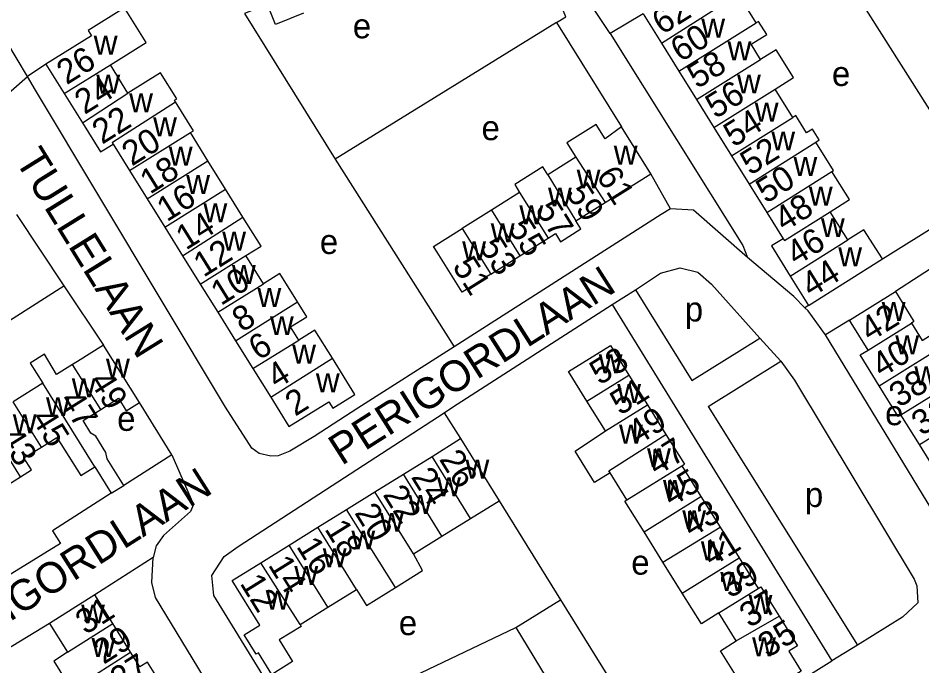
# Model space of a CAD drawing. Extents: x 157768 to 159790, y 387230 to 389604.
# Drawn here: x 158348.2 to 158494.9, y 388182.9 to 388288 of the extents above; entities that cross this region are included whole.
import ezdxf

# ---------------------------------------------------------------- set-up
doc = ezdxf.new("R2010")
doc.units = 0
for name, color, linetype in [('BLT_Basislijn', 7, 'Continuous'), ('BLT_Bebouwing', 7, 'Continuous'), ('BLT_Centroide', 7, 'Continuous'), ('BLT_Huisnummer', 7, 'Continuous'), ('BLT_Huisnummer_ tussenligend', 7, 'Continuous'), ('BLT_Onderverdeling_panden', 7, 'Continuous'), ('BLT_Straatnaam', 7, 'Continuous'), ('BLT_Vlakafsluiter', 7, 'Continuous')]:
    doc.layers.add(name, color=color, linetype=linetype)

msp = doc.modelspace()

# ---------------------------------------------------------------- linework, layer by layer
at = {"layer": 'BLT_Basislijn'}
for p, q in [((158384.98, 388288.7), (158399.69, 388265.08)), ((158449.67, 388288.69), (158444.32, 388285.49)), ((158435.6, 388287.24), (158399.69, 388265.08)), ((158435.6, 388287.24), (158446.18, 388270.31)), ((158352.71, 388280.51), (158349.72, 388278.49)), ((158399.69, 388265.08), (158418.98, 388234.63)), ((158454.1, 388257.02), (158450.94, 388262.72)), ((158488.57, 388248.89), (158505.07, 388259.33)), ((158347.92, 388256.11), (158355.63, 388244.55)), ((158507.94, 388254.9), (158490.64, 388243.59)), ((158312.55, 388217.11), (158355.63, 388244.55)), ((158355.63, 388244.55), (158362.06, 388234.91)), ((158444.66, 388241.5), (158448.43, 388243.86)), ((158448.43, 388243.86), (158457.61, 388229.19)), ((158444.66, 388241.5), (158480.34, 388183.69)), ((158476.52, 388241.37), (158475.94, 388240.99)), ((158483.19, 388238.98), (158479.29, 388236.6)), ((158497.32, 388207), (158479.29, 388236.6)), ((158457.61, 388229.19), (158468.65, 388236.06)), ((158460.26, 388224.95), (158472.05, 388232.29)), ((158373.16, 388217.13), (158367.88, 388225.6)), ((158460.26, 388224.95), (158484.49, 388186.23)), ((158417.37, 388223.95), (158420.03, 388219.74)), ((158373.16, 388217.13), (158365.35, 388212.14)), ((158426.29, 388209.66), (158436.28, 388193.58)), ((158370.1, 388200.44), (158360.66, 388194.37)), ((158428.99, 388189.09), (158436.28, 388193.58)), ((158436.28, 388193.58), (158453.03, 388166.65)), ((158353.29, 388189.74), (158336.07, 388179.24)), ((158408.94, 388179.51), (158428.99, 388189.09)), ((158428.99, 388189.09), (158445.59, 388162)), ((158484.49, 388186.23), (158480.34, 388183.69))]:
    msp.add_line(p, q, dxfattribs=at)
for points in [[(158349.72, 388278.49), (158346.36, 388284.12), (158345.87, 388286.78), (158346.16, 388288.41), (158347.49, 388290.13), (158351.49, 388293.04), (158382.15, 388309.1), (158406.63, 388320.52), (158418.95, 388325.92), (158458.67, 388342.3), (158495.06, 388356.91), (158496.09, 388357.31), (158498.9, 388357.63), (158500.72, 388357.63), (158504.55, 388356.37)], [(158444.32, 388285.49), (158436.68, 388296.95), (158434.42, 388302.8)], [(158435.6, 388287.24), (158437.14, 388288.19), (158431.35, 388302.19)], [(158497.8, 388270.57), (158497.61, 388270.86), (158478.88, 388300.51)], [(158444.32, 388285.49), (158465.87, 388251.07), (158466.61, 388249.14)], [(158418.98, 388234.63), (158403.33, 388224.67), (158396.24, 388220.06), (158392.33, 388217.68), (158390.41, 388216.95), (158389.21, 388216.88), (158387.35, 388217.31), (158386.16, 388218.18), (158381.87, 388224.86), (158351.02, 388276.29), (158349.72, 388278.49)], [(158454.1, 388257.02), (158452.61, 388256.13), (158418.98, 388234.63)], [(158466.61, 388249.14), (158457.87, 388256.8), (158454.1, 388257.02)], [(158475.94, 388240.99), (158474.13, 388242.81), (158466.61, 388249.14)], [(158448.43, 388243.86), (158452.5, 388246.58), (158455.69, 388247.43), (158458.57, 388246.74), (158460.76, 388244.81), (158468.65, 388236.06)], [(158417.37, 388223.95), (158418.74, 388224.84), (158444.66, 388241.5)], [(158479.29, 388236.6), (158476.45, 388240.48), (158475.94, 388240.99)], [(158468.65, 388236.06), (158472.05, 388232.29)], [(158472.05, 388232.29), (158474.24, 388229.24), (158493.66, 388196.96), (158494.14, 388195.85), (158494.27, 388193.09), (158491.78, 388190.76), (158484.49, 388186.23)], [(158395.91, 388168.42), (158379.98, 388194.29), (158379.66, 388197.53), (158381.67, 388200.59), (158383.9, 388202.25), (158417.37, 388223.95)], [(158373.16, 388217.13), (158376.69, 388209.04), (158376.21, 388207.92), (158371.8, 388204.02), (158370.63, 388202.35), (158370.1, 388200.44)], [(158363.32, 388210.88), (158353.8, 388204.8), (158355.1, 388202.71), (158342.47, 388194.97)], [(158385.74, 388166.03), (158387, 388166.8), (158370.49, 388193.98), (158369.92, 388196.38), (158370.1, 388200.44)], [(158453.03, 388166.65), (158454.49, 388167.56), (158480.34, 388183.69)]]:
    msp.add_lwpolyline(points, dxfattribs=at)
at = {"layer": 'BLT_Bebouwing'}
for p, q in [((158449.67, 388288.69), (158452.64, 388283.92)), ((158452.64, 388283.92), (158455.48, 388279.37)), ((158352.71, 388280.51), (158355.68, 388275.76)), ((158366.02, 388275.82), (158363.18, 388280.38)), ((158455.48, 388279.37), (158458.33, 388274.78)), ((158473.97, 388271.85), (158471.11, 388276.44)), ((158355.68, 388275.76), (158358.64, 388271.01)), ((158458.33, 388274.78), (158461.18, 388270.2)), ((158379.02, 388264.8), (158376.17, 388269.39)), ((158450.94, 388262.72), (158446.18, 388270.31)), ((158461.18, 388270.2), (158464.04, 388265.61)), ((158363.62, 388267.52), (158366.29, 388263.24)), ((158381.87, 388260.24), (158379.02, 388264.8)), ((158438.76, 388265.41), (158434.21, 388262.56)), ((158464.04, 388265.61), (158466.89, 388261.04)), ((158366.29, 388263.24), (158369.14, 388258.67)), ((158443.53, 388258.08), (158450.94, 388262.72)), ((158384.7, 388255.69), (158381.87, 388260.24)), ((158466.89, 388261.04), (158469.74, 388256.45)), ((158369.14, 388258.67), (158372, 388254.07)), ((158429.63, 388259.69), (158425.07, 388256.83)), ((158438.74, 388255.07), (158443.53, 388258.08)), ((158425.07, 388256.83), (158420.3, 388253.83)), ((158469.74, 388256.45), (158472.4, 388252.18)), ((158482.94, 388251.99), (158480.02, 388256.54)), ((158374.9, 388249.42), (158377.78, 388244.8)), ((158388.04, 388244.87), (158385.18, 388249.44)), ((158424.94, 388246.43), (158429.68, 388249.4)), ((158476.52, 388241.37), (158488.57, 388248.89)), ((158473.56, 388246.12), (158476.52, 388241.37)), ((158377.78, 388244.8), (158380.62, 388240.24)), ((158483.19, 388238.98), (158490.64, 388243.59)), ((158380.62, 388240.24), (158383.49, 388235.63)), ((158486.21, 388234.12), (158483.19, 388238.98)), ((158383.49, 388235.63), (158386.31, 388231.12)), ((158367.88, 388225.6), (158362.06, 388234.91)), ((158386.31, 388231.12), (158389.21, 388226.47)), ((158447.37, 388230.05), (158450.37, 388225.23)), ((158352.2, 388228.75), (158347.38, 388225.73)), ((158443.57, 388220.99), (158440.56, 388225.81)), ((158450.37, 388225.23), (158453.37, 388220.42)), ((158415.4, 388216.86), (158420.03, 388219.74)), ((158453.37, 388220.42), (158456.37, 388215.6)), ((158497.26, 388214.39), (158494.53, 388218.79)), ((158410.77, 388213.98), (158415.4, 388216.86)), ((158360.63, 388215.18), (158363.32, 388210.88)), ((158455.95, 388215.34), (158456.37, 388215.6)), ((158455.95, 388215.34), (158459.05, 388210.36)), ((158406.13, 388211.1), (158410.77, 388213.98)), ((158363.32, 388210.88), (158365.35, 388212.14)), ((158401.5, 388208.23), (158406.13, 388211.1)), ((158459.05, 388210.36), (158462.16, 388205.38)), ((158421.66, 388206.79), (158426.29, 388209.66)), ((158396.86, 388205.35), (158401.5, 388208.23)), ((158417.02, 388203.91), (158421.66, 388206.79)), ((158392.23, 388202.47), (158396.86, 388205.35)), ((158462.16, 388205.38), (158465.26, 388200.4)), ((158412.39, 388201.03), (158417.02, 388203.91)), ((158387.59, 388199.59), (158392.23, 388202.47)), ((158465.26, 388200.4), (158468.36, 388195.41)), ((158360.66, 388194.37), (158353.29, 388189.74)), ((158363.56, 388189.74), (158360.66, 388194.37)), ((158398.49, 388192.39), (158403.12, 388195.27)), ((158394, 388189.6), (158398.49, 388192.39)), ((158464.81, 388186.92), (158461.99, 388191.45)), ((158366.47, 388185.11), (158363.56, 388189.74))]:
    msp.add_line(p, q, dxfattribs=at)
for points in [[(158468.03, 388287.19), (158465.14, 388291.84), (158462.61, 388290.24)], [(158365.47, 388289.67), (158359.55, 388285.99), (158360.09, 388285.11), (158352.71, 388280.51)], [(158363.18, 388280.38), (158369.01, 388284.03), (158365.47, 388289.67)], [(158394.54, 388288.77), (158389.99, 388286.93), (158388.67, 388290.19), (158384.98, 388288.7)], [(158468.76, 388281.28), (158467.21, 388283.77), (158469.74, 388285.34), (158468.43, 388287.44), (158468.03, 388287.19)], [(158471.11, 388276.44), (158474.11, 388278.32), (158471.3, 388282.85), (158468.76, 388281.28)], [(158373.76, 388274.37), (158373.59, 388274.64), (158373.96, 388274.87), (158371.31, 388279.12), (158366.02, 388275.82)], [(158376.17, 388269.39), (158376.67, 388269.7), (158373.76, 388274.37)], [(158477.71, 388267.85), (158478.27, 388268.2), (158477.16, 388269.98), (158476.18, 388269.37), (158474.45, 388272.15), (158473.97, 388271.85)], [(158358.64, 388271.01), (158361.6, 388266.26), (158363.62, 388267.52)], [(158446.18, 388270.31), (158443.53, 388268.4), (158442.07, 388270.73), (158437.3, 388267.74), (158438.76, 388265.41)], [(158480.31, 388263.08), (158480.59, 388263.26), (158477.71, 388267.85)], [(158434.21, 388262.56), (158433.42, 388263.83), (158428.84, 388260.96), (158429.63, 388259.69)], [(158480.02, 388256.54), (158483.17, 388258.52), (158480.31, 388263.08)], [(158385.18, 388249.44), (158387.64, 388250.97), (158384.7, 388255.69)], [(158434.26, 388252.27), (158435.43, 388253), (158436.25, 388251.7), (158439.55, 388253.77), (158438.74, 388255.07)], [(158372, 388254.07), (158374.9, 388249.42)], [(158424.94, 388246.43), (158420.29, 388243.51), (158416.23, 388250), (158415.65, 388250.92), (158420.3, 388253.83)], [(158488.57, 388248.89), (158485.54, 388253.61), (158482.94, 388251.99)], [(158429.68, 388249.4), (158430.64, 388250), (158434.26, 388252.27)], [(158472.4, 388252.18), (158470.52, 388251.02), (158473.56, 388246.12)], [(158393.55, 388241.96), (158390.7, 388246.53), (158388.04, 388244.87)], [(158490.64, 388243.59), (158493.65, 388238.73), (158493.25, 388238.48)], [(158393.75, 388235.7), (158392.4, 388237.87), (158395.06, 388239.53), (158393.55, 388241.96)], [(158493.25, 388238.48), (158494.98, 388235.68), (158497.19, 388237.05), (158498.49, 388234.95), (158496.34, 388233.49)], [(158399.22, 388232.79), (158396.38, 388237.34), (158393.75, 388235.7)], [(158362.06, 388234.91), (158357.82, 388232.26), (158357.05, 388231.78)], [(158440.56, 388225.81), (158437.56, 388230.63), (158444.37, 388234.87), (158447.37, 388230.05)], [(158488, 388228.33), (158484.91, 388233.32), (158486.21, 388234.12)], [(158357.05, 388231.78), (158354.43, 388230.14), (158352.49, 388233.42), (158350.17, 388231.99), (158352.2, 388228.75)], [(158389.21, 388226.47), (158392.18, 388221.7), (158398.64, 388225.72), (158399.29, 388224.69), (158402.88, 388226.92), (158399.22, 388232.79)], [(158491.53, 388223.62), (158491.09, 388223.35), (158488, 388228.33)], [(158361.62, 388224.48), (158364.49, 388226.28), (158365.75, 388224.27), (158367.88, 388225.6)], [(158365.35, 388212.14), (158362.65, 388216.44), (158362.45, 388217.51), (158360.82, 388220.12), (158360.03, 388220.62), (158358.74, 388222.69), (158361.62, 388224.48)], [(158494.53, 388218.79), (158491.53, 388223.62)], [(158444.3, 388214.2), (158441.8, 388212.64), (158438.63, 388217.72), (158443.57, 388220.99)], [(158351.98, 388218.38), (158354.49, 388219.95), (158358.36, 388213.76), (158360.63, 388215.18)], [(158420.03, 388219.74), (158422.67, 388215.49), (158426.29, 388209.66)], [(158348.58, 388213.55), (158350.35, 388214.66), (158349.13, 388216.61), (158351.98, 388218.38)], [(158344.99, 388208.46), (158346.78, 388209.58), (158345.5, 388211.62), (158348.58, 388213.55)], [(158447.04, 388209.79), (158444.3, 388214.2)], [(158449.83, 388204.61), (158446.73, 388209.59), (158447.04, 388209.79)], [(158452.9, 388199.68), (158449.83, 388204.61)], [(158409.46, 388195.58), (158413.88, 388198.32), (158412.39, 388201.03)], [(158394, 388189.6), (158394.17, 388189.25), (158390.58, 388187.08), (158392.76, 388183.57), (158389.4, 388181.47), (158387.21, 388184.99), (158386.87, 388184.78), (158384.92, 388187.91), (158387.45, 388189.48), (158382.96, 388196.71), (158387.59, 388199.59)], [(158456.03, 388194.65), (158452.9, 388199.68)], [(158403.12, 388195.27), (158404.77, 388192.66), (158409.46, 388195.58)], [(158468.36, 388195.41), (158468.79, 388195.68), (158471.76, 388190.91)], [(158459.14, 388189.67), (158456.03, 388194.65)], [(158461.99, 388191.45), (158459.14, 388189.67)], [(158353.29, 388189.74), (158355.95, 388185.51), (158356.2, 388185.11)], [(158471.76, 388190.91), (158474.73, 388186.14), (158473.31, 388185.25), (158475.33, 388182.01), (158467.39, 388177.06), (158462.24, 388185.33), (158464.81, 388186.92)], [(158356.2, 388185.11), (158354.01, 388183.63), (158355.97, 388180.5), (158354.01, 388179.27), (158354.92, 388177.81), (158356.63, 388178.88)], [(158370.55, 388181.29), (158369.18, 388183.49), (158367.96, 388182.73), (158366.47, 388185.11)]]:
    msp.add_lwpolyline(points, dxfattribs=at)
at = {"layer": 'BLT_Onderverdeling_panden'}
for p, q in [((158452.64, 388283.92), (158462.61, 388290.24)), ((158455.48, 388279.37), (158468.03, 388287.19)), ((158458.33, 388274.78), (158468.76, 388281.28)), ((158355.68, 388275.76), (158363.18, 388280.38)), ((158461.18, 388270.2), (158471.11, 388276.44)), ((158358.64, 388271.01), (158366.02, 388275.82)), ((158464.04, 388265.61), (158473.97, 388271.85)), ((158366.29, 388263.24), (158376.17, 388269.39)), ((158466.89, 388261.04), (158477.71, 388267.85)), ((158369.14, 388258.67), (158379.02, 388264.8)), ((158438.76, 388265.41), (158443.53, 388258.08)), ((158469.74, 388256.45), (158480.31, 388263.08)), ((158434.21, 388262.56), (158438.74, 388255.07)), ((158372, 388254.07), (158381.87, 388260.24)), ((158429.63, 388259.69), (158434.26, 388252.27)), ((158374.9, 388249.42), (158384.7, 388255.69)), ((158425.07, 388256.83), (158429.68, 388249.4)), ((158420.3, 388253.83), (158424.94, 388246.43)), ((158473.56, 388246.12), (158482.94, 388251.99)), ((158377.78, 388244.8), (158385.18, 388249.44)), ((158380.62, 388240.24), (158388.04, 388244.87)), ((158383.49, 388235.63), (158393.55, 388241.96)), ((158486.21, 388234.12), (158493.25, 388238.48)), ((158386.31, 388231.12), (158393.75, 388235.7)), ((158389.21, 388226.47), (158399.22, 388232.79)), ((158488, 388228.33), (158496.34, 388233.49)), ((158361.62, 388224.48), (158357.05, 388231.78)), ((158440.56, 388225.81), (158447.37, 388230.05)), ((158360.63, 388215.18), (158352.2, 388228.75)), ((158491.53, 388223.62), (158499.42, 388228.51)), ((158351.98, 388218.38), (158347.38, 388225.73)), ((158443.57, 388220.99), (158450.37, 388225.23)), ((158494.53, 388218.79), (158505.42, 388225.54)), ((158348.58, 388213.55), (158342.71, 388222.82)), ((158421.66, 388206.79), (158415.4, 388216.86)), ((158447.04, 388209.79), (158455.95, 388215.34)), ((158417.02, 388203.91), (158410.77, 388213.98)), ((158412.39, 388201.03), (158406.13, 388211.1)), ((158449.83, 388204.61), (158459.05, 388210.36)), ((158409.46, 388195.58), (158401.5, 388208.23)), ((158403.12, 388195.27), (158396.86, 388205.35)), ((158452.9, 388199.68), (158462.16, 388205.38)), ((158398.49, 388192.39), (158392.23, 388202.47)), ((158458.89, 388196.43), (158465.26, 388200.4)), ((158394, 388189.6), (158387.59, 388199.59)), ((158456.03, 388194.65), (158458.89, 388196.43)), ((158461.99, 388191.45), (158468.36, 388195.41)), ((158356.2, 388185.11), (158363.56, 388189.74)), ((158464.81, 388186.92), (158471.76, 388190.91)), ((158356.63, 388178.88), (158366.47, 388185.11))]:
    msp.add_line(p, q, dxfattribs=at)
for points in [[(158363.62, 388267.52), (158363.52, 388267.86), (158373.76, 388274.37)], [(158472.4, 388252.18), (158472.61, 388251.9), (158480.02, 388256.54)], [(158444.3, 388214.2), (158444.11, 388214.49), (158453.37, 388220.42)]]:
    msp.add_lwpolyline(points, dxfattribs=at)
at = {"layer": 'BLT_Vlakafsluiter'}
msp.add_line((158339.49, 388269.6), (158349.72, 388278.49), dxfattribs=at)

# ---------------------------------------------------------------- texts
at = {"layer": 'BLT_Centroide'}
for s, p in [('e', (158402.54, 388284.7)), ('w', (158459.12, 388284.81)), ('w', (158360.48, 388282.03)), ('w', (158463.39, 388281.12)), ('e', (158480.34, 388276.96)), ('w', (158360.9, 388275.72)), ('w', (158464.93, 388275.75)), ('w', (158366.23, 388272.69)), ('w', (158467.8, 388271.19)), ('w', (158370.12, 388268.81)), ('e', (158423.44, 388268.17)), ('w', (158470.49, 388266.5)), ('w', (158372.66, 388264.03)), ('w', (158444.91, 388264.2)), ('w', (158474.09, 388262.38)), ('w', (158438.89, 388260.33)), ('w', (158375.49, 388259.44)), ('w', (158434.23, 388257.41)), ('w', (158476.59, 388257.56)), ('w', (158378.29, 388254.84)), ('w', (158429.59, 388254.5)), ('w', (158424.94, 388251.59)), ('w', (158478.55, 388252.44)), ('w', (158381.34, 388250.25)), ('e', (158397.19, 388249.7)), ('w', (158420.3, 388248.67)), ('w', (158481.36, 388247.72)), ('w', (158382.92, 388244.84)), ('w', (158387.06, 388241.09)), ('p', (158456.44, 388238.75)), ('w', (158488.42, 388238.84)), ('w', (158389.09, 388236.53)), ('w', (158490.62, 388233.41)), ('w', (158392.7, 388231.91)), ('w', (158362.47, 388229.62)), ('w', (158442.47, 388230.34)), ('w', (158493.71, 388228.41)), ('w', (158356.91, 388226.45)), ('w', (158396.55, 388227.25)), ('w', (158445.47, 388225.53)), ('w', (158352.72, 388223.39)), ('e', (158488.97, 388221.92)), ('w', (158347.34, 388220.61)), ('e', (158364.28, 388221)), ('w', (158445.77, 388218.94)), ('w', (158450.32, 388215.09)), ('w', (158420.84, 388213.27)), ('w', (158416.22, 388210.39)), ('w', (158452.89, 388209.97)), ('p', (158475.95, 388208.65)), ('w', (158411.58, 388207.52)), ('w', (158406.94, 388204.62)), ('w', (158456.03, 388205.03)), ('w', (158402.31, 388201.75)), ('w', (158459.05, 388200)), ('w', (158397.67, 388198.86)), ('e', (158447.75, 388197.67)), ('w', (158393.05, 388195.98)), ('w', (158462.2, 388195.03)), ('w', (158388.41, 388192)), ('w', (158466.8, 388191.31)), ('w', (158358.43, 388189.75)), ('e', (158410.01, 388187.85)), ('w', (158360.12, 388184.31)), ('w', (158467.38, 388184.41))]:
    msp.add_text(s, height=4, dxfattribs=at).set_placement(p)
at = {"layer": 'BLT_Huisnummer'}
for s, rotation, p in [('62', 31.9007, (158452.75, 388285.18)), ('26', 31.9331, (158356.08, 388277.07)), ('56', 31.9007, (158461.42, 388271.56)), ('22', 31.9331, (158361.84, 388267.41)), ('52', 31.9007, (158467.07, 388262.36)), ('18', 31.9331, (158369.61, 388259.31)), ('61', 302.0887, (158441.97, 388262.39)), ('48', 31.9007, (158472.6, 388253.22)), ('14', 31.9331, (158375.44, 388250.24)), ('55', 302.0908, (158427.61, 388253.96)), ('51', 302.0839, (158418.61, 388247.71)), ('44', 31.9007, (158476.95, 388242.56)), ('10', 31.9331, (158381.12, 388241.24)), ('42', 31.7709, (158486.52, 388235.36)), ('6', 31.9331, (158387.24, 388232.33)), ('53', 31.9159, (158442.62, 388228.32)), ('49', 302.0228, (158359.68, 388229.1)), ('2', 31.9331, (158393.18, 388223.28)), ('36', 31.7709, (158494.86, 388220.1)), ('45', 302.0228, (158350.23, 388223.05)), ('47', 31.9159, (158451.89, 388213.59)), ('26', 301.851, (158416.48, 388216.4)), ('20', 301.851, (158402.73, 388207.71)), ('43', 31.9159, (158457.54, 388203.57)), ('16', 301.851, (158393.28, 388202.25)), ('39', 31.9159, (158463.8, 388193.73)), ('12', 301.851, (158384.11, 388196.27)), ('31', 32.1164, (158359.15, 388187.83)), ('35', 31.9159, (158469.93, 388184.09))]:
    msp.add_text(s, height=4, rotation=rotation, dxfattribs=at).set_placement(p)
at = {"layer": 'BLT_Huisnummer_ tussenligend'}
for s, rotation, p in [('60', 31.9007, (158455.75, 388280.73)), ('58', 31.9007, (158458.46, 388276.42)), ('24', 31.9331, (158358.99, 388272.25)), ('54', 31.9007, (158464.36, 388266.93)), ('20', 31.9331, (158366.66, 388263.87)), ('50', 31.9007, (158469.63, 388257.8)), ('16', 31.9331, (158372.34, 388254.83)), ('59', 302.0908, (158437.04, 388259.63)), ('57', 302.0908, (158432.05, 388256.94)), ('46', 31.9007, (158474.52, 388247.68)), ('12', 31.9331, (158378.3, 388245.83)), ('53', 302.0839, (158422.95, 388250.93)), ('8', 31.9331, (158384.56, 388236.92)), ('40', 31.7709, (158488.39, 388229.53)), ('4', 31.9331, (158390.2, 388227.72)), ('38', 31.7709, (158491.23, 388224.68)), ('51', 31.9159, (158445.94, 388223.42)), ('47', 302.0228, (158354.81, 388226.03)), ('49', 31.9159, (158448.79, 388218.59)), ('43', 302.0228, (158344.98, 388219.99)), ('24', 301.851, (158411.91, 388213.52)), ('45', 31.9159, (158454.3, 388208.56)), ('22', 301.851, (158407.33, 388210.67)), ('18', 301.851, (158397.87, 388205.08)), ('41', 31.9159, (158460.81, 388198.84)), ('14', 301.851, (158388.7, 388199.25)), ('37', 31.9159, (158466.95, 388188.95)), ('29', 32.1164, (158362.08, 388183.03)), ('27', 32.1164, (158364.77, 388178.57))]:
    msp.add_text(s, height=4, rotation=rotation, dxfattribs=at).set_placement(p)
at = {"layer": 'BLT_Straatnaam'}
for s, rotation, p in [('TULLELAAN', 301.8387, (158347.6, 388264.92)), ('PERIGORDLAAN', 32.4225, (158400.73, 388215.29)), ('PERIGORDLAAN', 32.4225, (158335.21, 388182.57))]:
    msp.add_text(s, height=5, rotation=rotation, dxfattribs=at).set_placement(p)

doc.saveas('drawing.dxf')
